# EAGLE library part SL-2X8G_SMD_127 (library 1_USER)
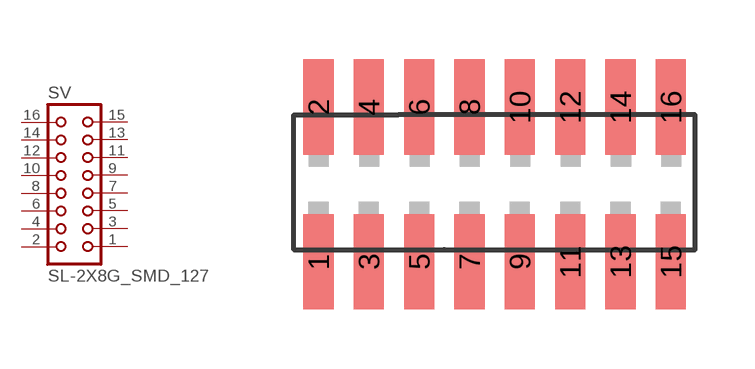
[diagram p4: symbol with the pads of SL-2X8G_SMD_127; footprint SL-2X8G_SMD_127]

Designator prefix SV

## SL-2X8G_SMD_127  [SL-2X8G_SMD_127]
1  1  pas
2  2  pas
3  3  pas
4  4  pas
5  5  pas
6  6  pas
7  7  pas
8  8  pas
9  9  pas
10  10  pas
11  11  pas
12  12  pas
13  13  pas
14  14  pas
15  15  pas
16  16  pas

## Footprint SL-2X8G_SMD_127 (pad centres in mm)
smd 0.76 x 2.4: 1 0,1.2; 2 0,5.1; 3 1.27,1.2; 4 1.27,5.1; 5 2.54,1.2; 6 2.54,5.1; 7 3.81,1.2; 8 3.81,5.1; 9 5.08,1.2; 10 5.08,5.1; 11 6.35,1.2; 12 6.35,5.1; 13 7.62,1.2; 14 7.62,5.1; 15 8.89,1.2; 16 8.89,5.1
